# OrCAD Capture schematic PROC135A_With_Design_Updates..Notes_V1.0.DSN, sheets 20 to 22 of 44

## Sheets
20 20. OSPI INTERFACE: size C; title: OSPI INTERFACE
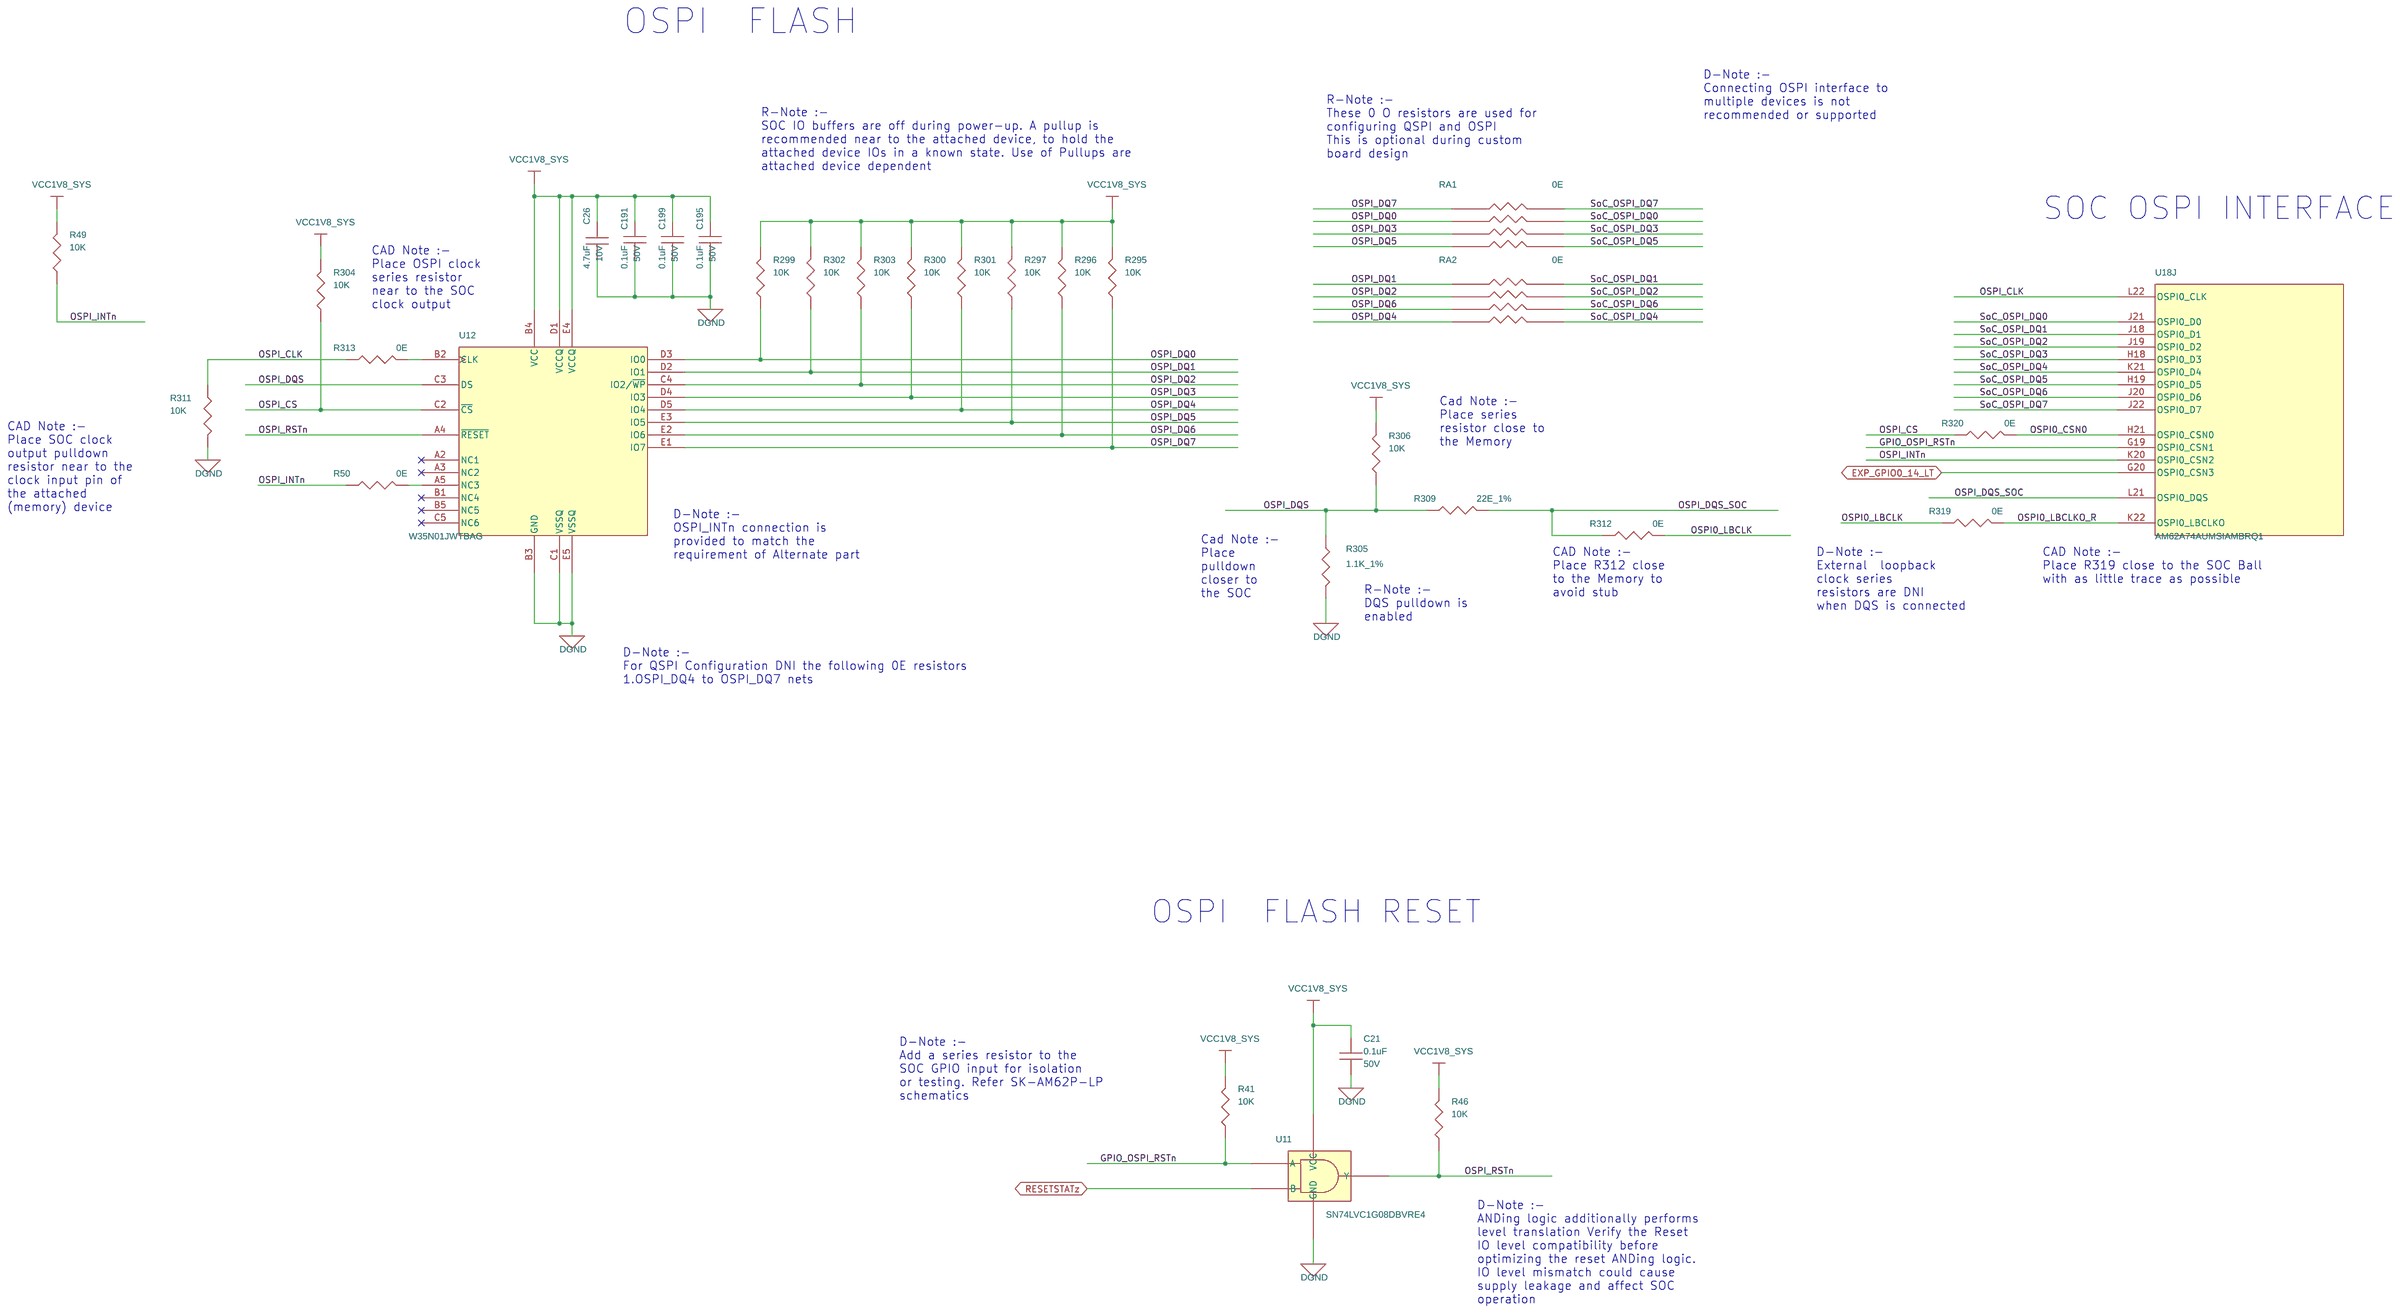
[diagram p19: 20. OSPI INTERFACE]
21 21. BRD ID EEPROM &TEMP SENSORS: size C; title: BOARD ID EEPROM & TEMPERATURE SENSORS
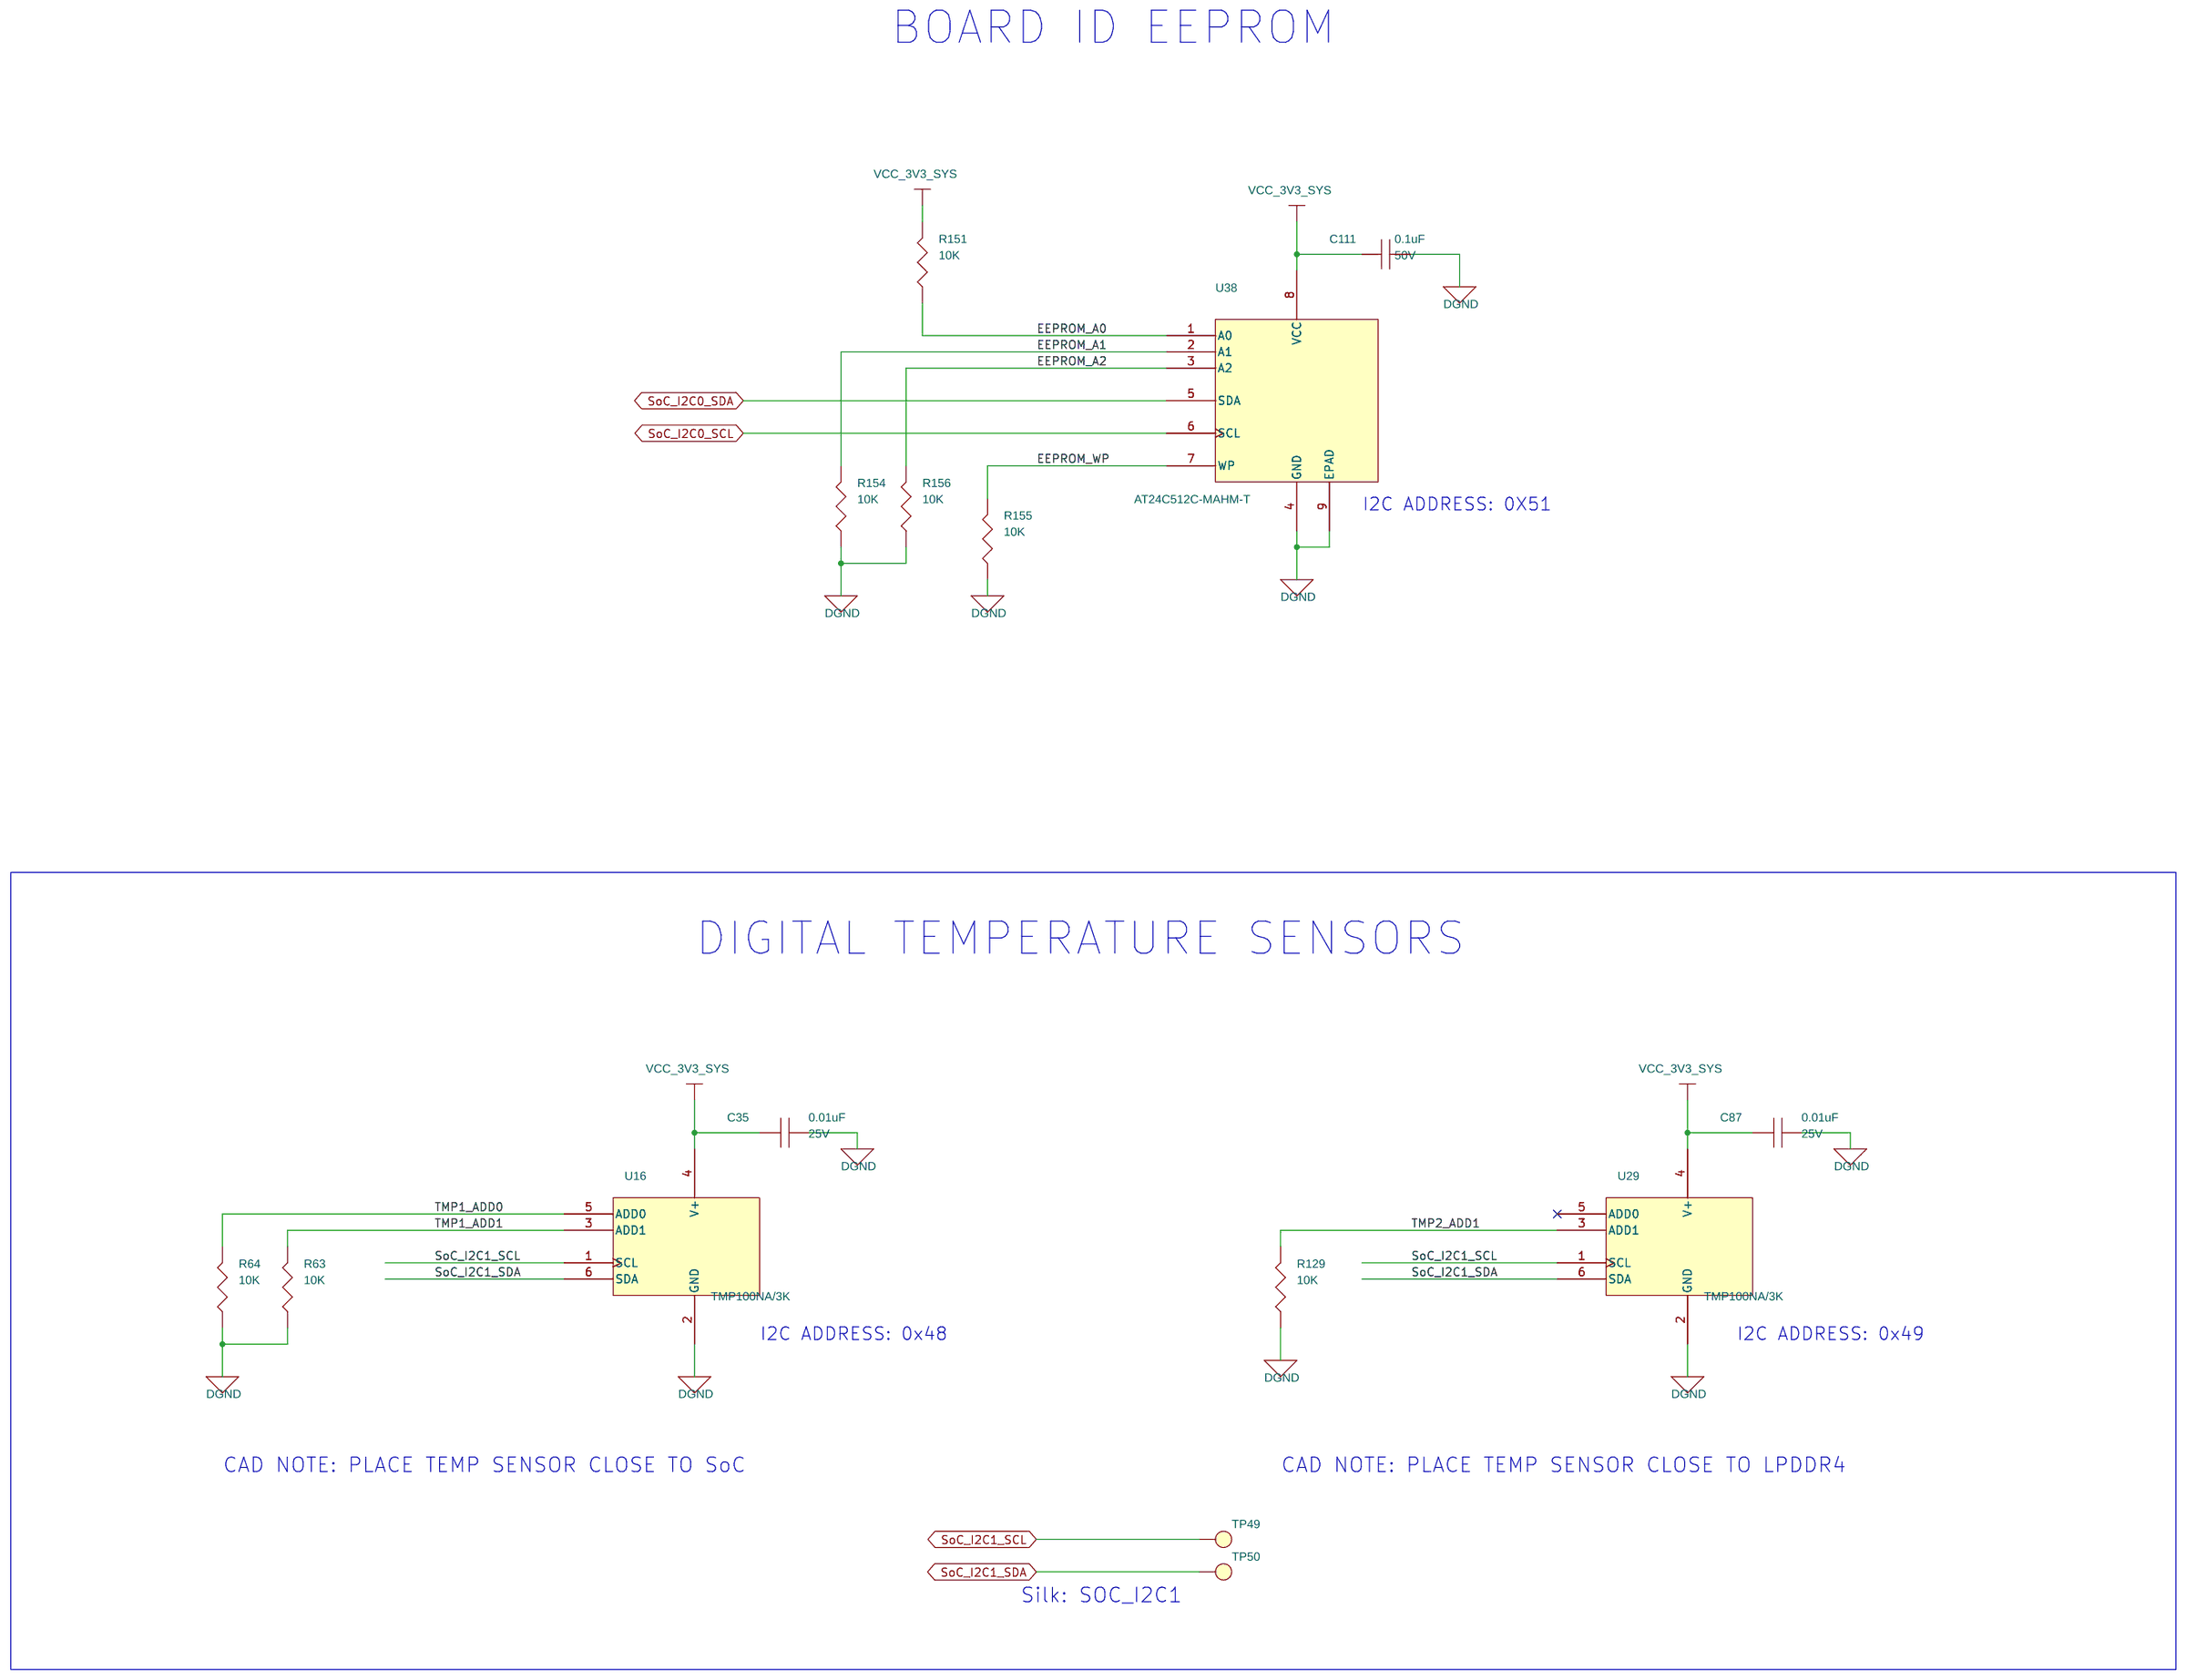
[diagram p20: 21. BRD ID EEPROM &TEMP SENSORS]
22 22. CPSW RGMII_1 ETHERNET PHY: size C; title: CPSW RGMII_1 ETHERNET PHY
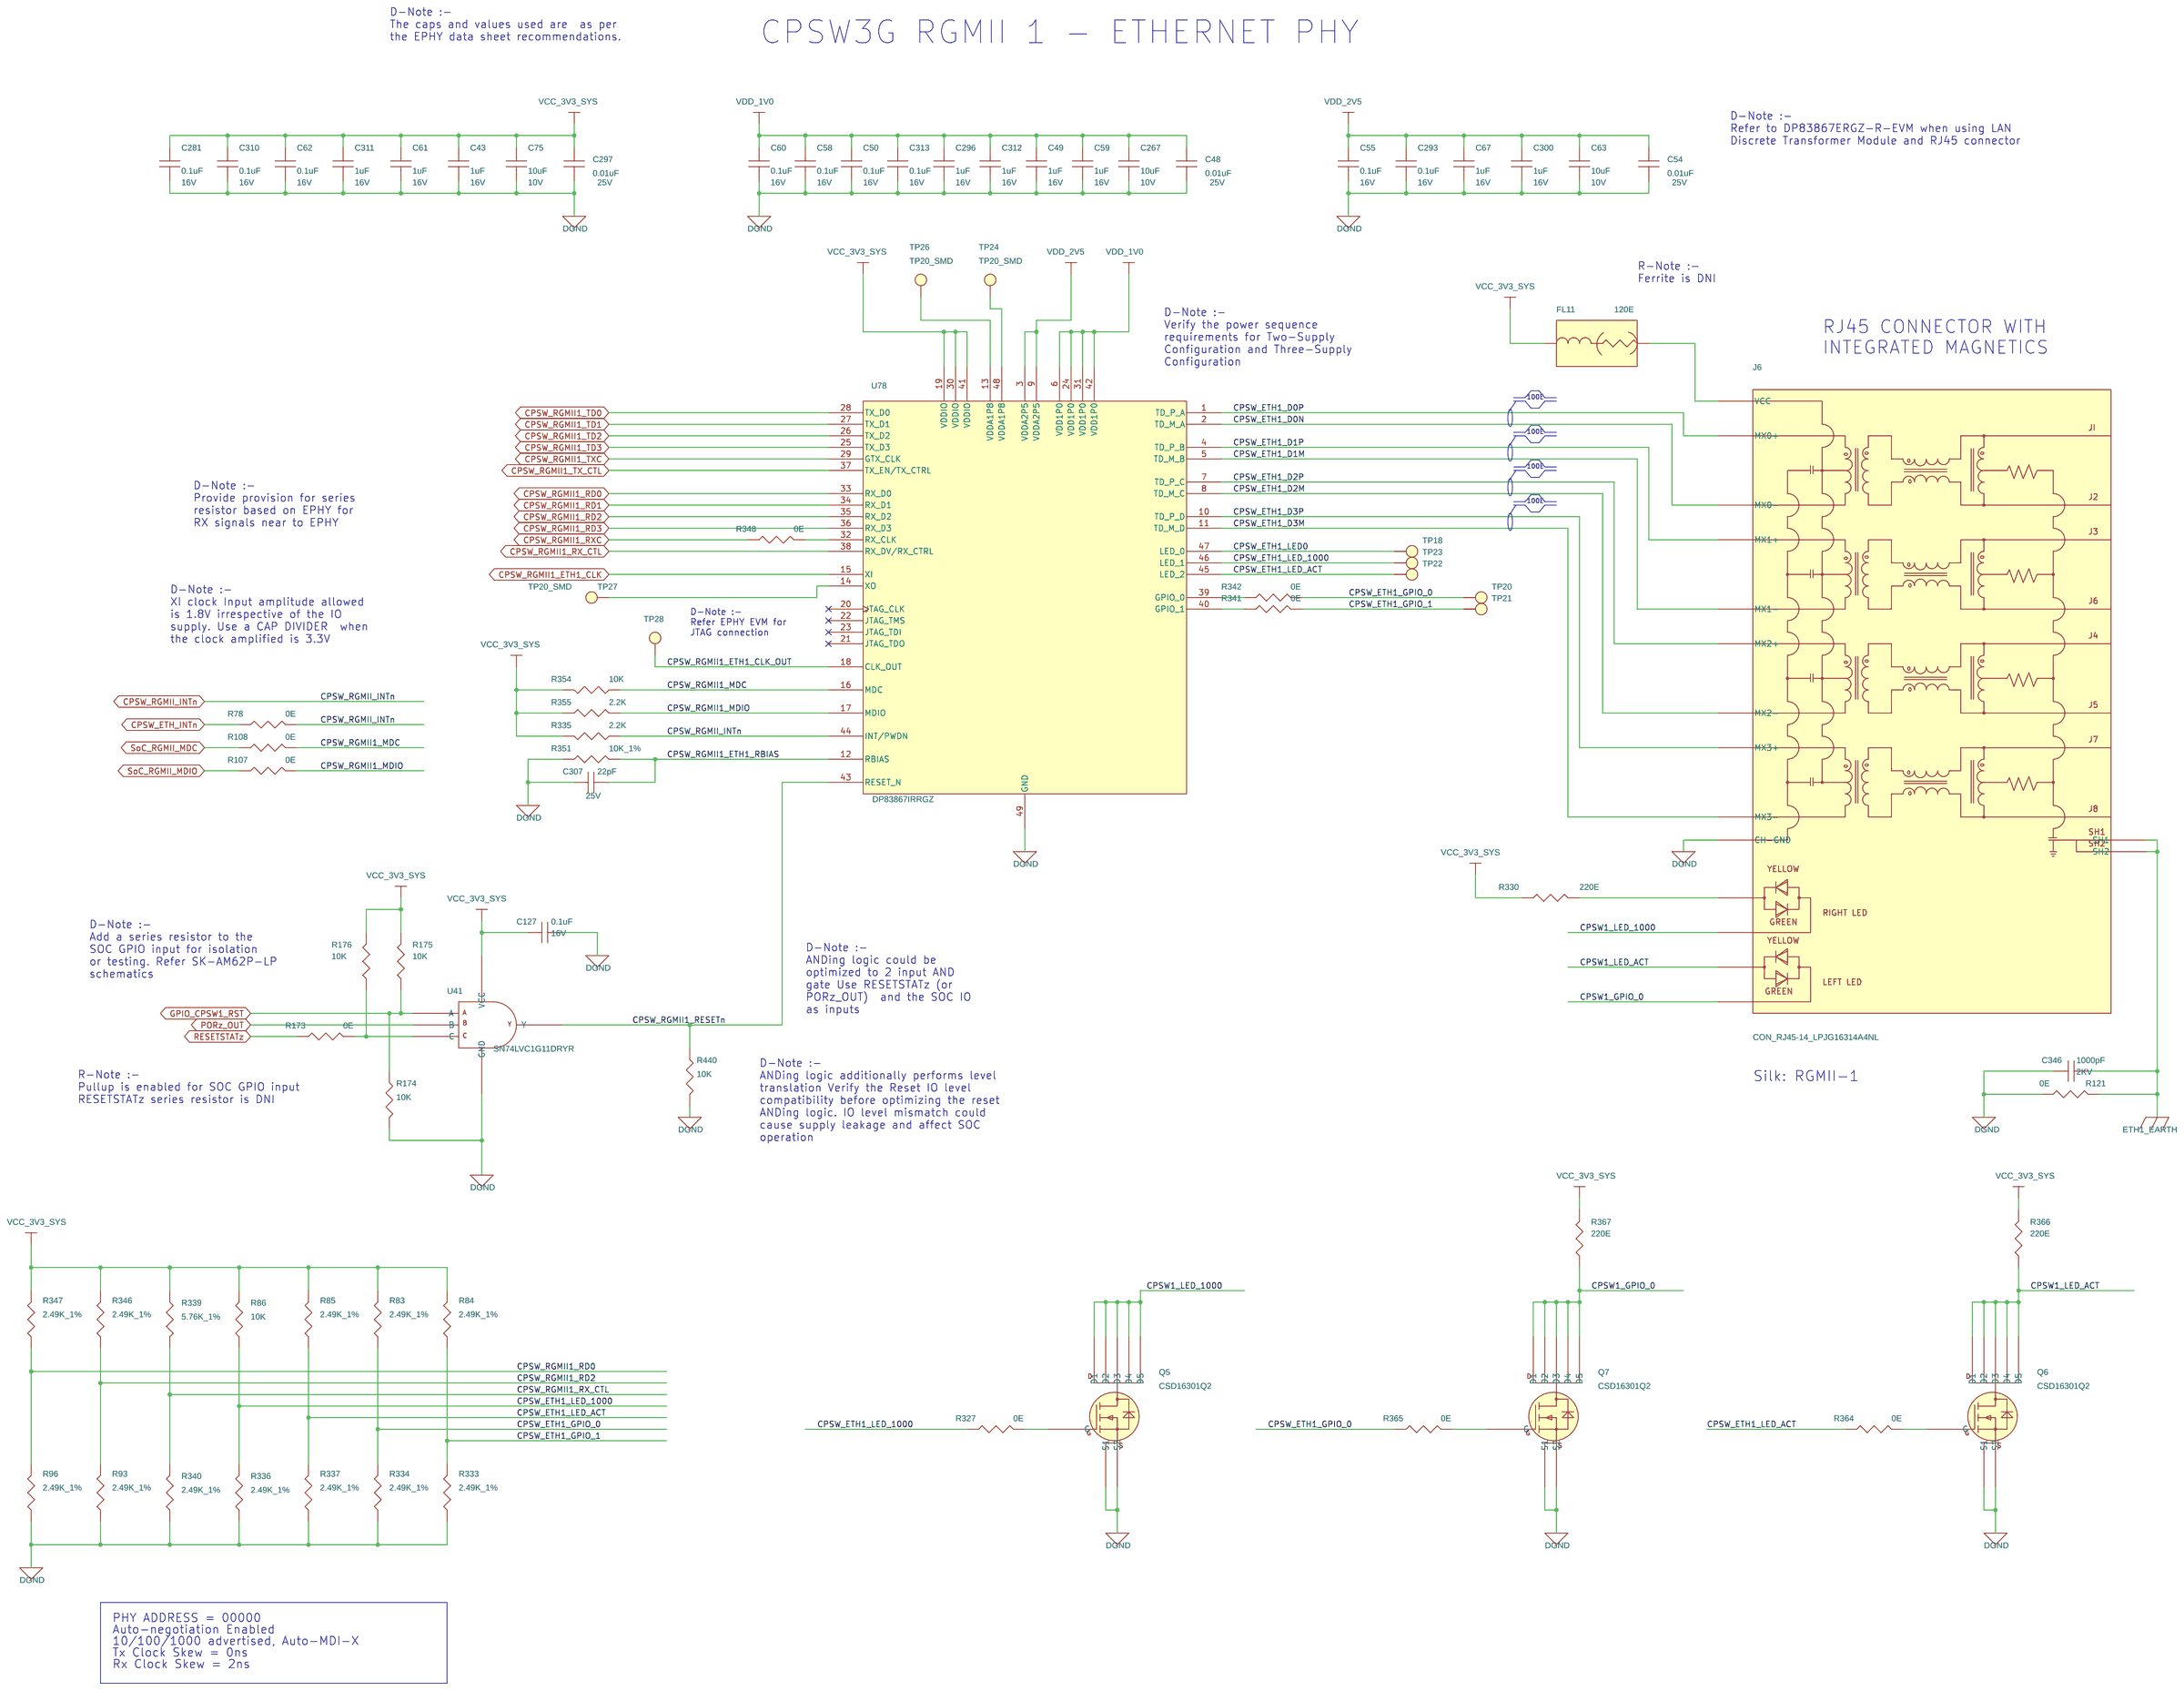
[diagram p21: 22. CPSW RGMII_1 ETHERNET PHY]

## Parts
sheet 20. OSPI INTERFACE
C21  0.1uF  [CAP0402_0-75]
C26  4.7uF  [CAP0402_0-75]
C191  0.1uF  [CAP0402_0-75]
C195  0.1uF  [CAP0402_0-75]
C199  0.1uF  [CAP0402_0-75]
R41  10K  [RES0201_0-5]
R46  10K  [RES0201_0-5]
R49  10K  [RES0201_0-5]
R50  0E  [RES0402_0-5]
R295  10K  [RES0201_0-5]
R296  10K  [RES0201_0-5]
R297  10K  [RES0201_0-5]
R299  10K  [RES0201_0-5]
R300  10K  [RES0201_0-5]
R301  10K  [RES0201_0-5]
R302  10K  [RES0201_0-5]
R303  10K  [RES0201_0-5]
R304  10K  [RES0201_0-5]
R305  1.1K_1%  [RES0201_0-5]
R306  10K  [RES0201_0-5]
R309  22E_1%  [RES0201_0-5]
R311  10K  [RES0201_0-5]
R312  0E  [RES0201_0-5]
R313  0E  [RES0402_0-5]
R319  0E  [RES0201_0-5]
R320  0E  [RES0201_0-5]
RA1  0E  [RESA_EXB_0201-4_0-5]
RA2  0E  [RESA_EXB_0201-4_0-5]
U11  SN74LVC1G08DBVRE4  [SOT23-5]
U12  W35N01JWTBAG  [TPBGA24_39-37_240X320_1-2]
sheet 21. BRD ID EEPROM &TEMP SENSORS
C35  0.01uF  [CAP0201_0-5]
C87  0.01uF  [CAP0201_0-5]
C111  0.1uF  [CAP0402_0-75]
R63  10K  [RES0201_0-5]
R64  10K  [RES0201_0-5]
R129  10K  [RES0201_0-5]
R151  10K  [RES0201_0-5]
R154  10K  [RES0201_0-5]
R155  10K  [RES0201_0-5]
R156  10K  [RES0201_0-5]
TP49  TP20_SMD  [TP20_SMD]
TP50  TP20_SMD  [TP20_SMD]
U16  TMP100NA/3K  [SOT23-6_1-5]
U29  TMP100NA/3K  [SOT23-6_1-5]
U38  AT24C512C-MAHM-T  [UDFN8_19-68_120X80_0-6]
sheet 22. CPSW RGMII_1 ETHERNET PHY
C43  1uF  [CAP0201_0-5]
C48  0.01uF  [CAP0201_0-5]
C49  1uF  [CAP0201_0-5]
C50  0.1uF  [CAP0201_0-5]
C54  0.01uF  [CAP0201_0-5]
C55  0.1uF  [CAP0201_0-5]
C58  0.1uF  [CAP0201_0-5]
C59  1uF  [CAP0201_0-5]
C60  0.1uF  [CAP0201_0-5]
C61  1uF  [CAP0201_0-5]
C62  0.1uF  [CAP0201_0-5]
C63  10uF  [CAP0402_0-75]
C67  1uF  [CAP0201_0-5]
C75  10uF  [CAP0402_0-75]
C127  0.1uF  [CAP0201_0-5]
C267  10uF  [CAP0402_0-75]
C281  0.1uF  [CAP0201_0-5]
C293  0.1uF  [CAP0201_0-5]
C296  1uF  [CAP0201_0-5]
C297  0.01uF  [CAP0201_0-5]
C300  1uF  [CAP0201_0-5]
C307  22pF  [CAP0201_0-5]
C310  0.1uF  [CAP0201_0-5]
C311  1uF  [CAP0201_0-5]
C312  1uF  [CAP0201_0-5]
C313  0.1uF  [CAP0201_0-5]
C346  1000pF  [CAP1206_1-75]
FL11  120E  [EMIFIL_BLM15A_0402_0-6]
J6  CON_RJ45-14_LPJG16314A4NL  [CON_RJ45-14_LPJG16314A4NL_S_R_T_13-6]
Q5  CSD16301Q2  [WSON6_CSD13202Q2_80X80_0-8]
Q6  CSD16301Q2  [WSON6_CSD13202Q2_80X80_0-8]
Q7  CSD16301Q2  [WSON6_CSD13202Q2_80X80_0-8]
R78  0E  [RES0402_0-5]
R83  2.49K_1%  [RES0402_0-5]
R84  2.49K_1%  [RES0402_0-5]
R85  2.49K_1%  [RES0402_0-5]
R86  10K  [RES0201_0-5]
R93  2.49K_1%  [RES0402_0-5]
R96  2.49K_1%  [RES0402_0-5]
R107  0E  [RES0402_0-5]
R108  0E  [RES0402_0-5]
R121  0E  [RES0603_0-75]
R173  0E  [RES0201_0-5]
R174  10K  [RES0201_0-5]
R175  10K  [RES0201_0-5]
R176  10K  [RES0201_0-5]
R327  0E  [RES0201_0-5]
R330  220E  [RES0402_0-5]
R333  2.49K_1%  [RES0402_0-5]
R334  2.49K_1%  [RES0402_0-5]
R335  2.2K  [RES0201_0-5]
R336  2.49K_1%  [RES0402_0-5]
R337  2.49K_1%  [RES0402_0-5]
R339  5.76K_1%  [RES0402_0-5]
R340  2.49K_1%  [RES0402_0-5]
R341  0E  [RES0201_0-5]
R342  0E  [RES0201_0-5]
R346  2.49K_1%  [RES0402_0-5]
R347  2.49K_1%  [RES0402_0-5]
R348  0E  [RES0402_0-5]
R351  10K_1%  [RES0402_0-5]
R354  10K  [RES0201_0-5]
R355  2.2K  [RES0201_0-5]
R364  0E  [RES0201_0-5]
R365  0E  [RES0201_0-5]
R366  220E  [RES0402_0-5]
R367  220E  [RES0402_0-5]
R440  10K  [RES0201_0-5]
TP18  TP20_SMD  [TP20_SMD]
TP20  TP20_SMD  [TP20_SMD]
TP21  TP20_SMD  [TP20_SMD]
TP22  TP20_SMD  [TP20_SMD]
TP23  TP20_SMD  [TP20_SMD]
TP24  TP20_SMD  [TP20_SMD]
TP26  TP20_SMD  [TP20_SMD]
TP27  TP20_SMD  [TP20_SMD]
TP28  TP20_SMD  [TP20_SMD]
U41  SN74LVC1G11DRYR  [SON6_SN74LVC2G17_40X60_0-6]
U78  DP83867IRRGZ  [QFN48_19-68_280X280_1]
sheet 41. OSCILLATOR
U18  AM62A74AUMSIAMBRQ1  [FBGA484_31-49_710X710_2-7]  (sections A,B,C,D,E,F,G,H,I,J,K,L,M,N,O,P,Q)

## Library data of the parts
C21 C111 C191 C195 C199 = CAP: CAP CERAMIC 0.1uF 50V 10% X7R 0402; Alt_Mfr_name: YAGEO AMERICA; Alt_Mfr_part_number: CC0402KRX5R8BB104; Chkd/date: MANIRAJA/261020; Crtd /date: ALVY/211020; Custom_Duty: 15%; Customs_HS_Code: 85322990; Distributor_name: DIGIKEY; Distributor_part_number: 490-10700-1-ND; Footprint Path: Y:\MIS_DATABASE\Library\ALTIUM_TOOL\PCB_FOOTPRINTS\Altium_Footprint_Lib.PcbLib; Height: 0.55MM; Library Path: Y:\MIS_DATABASE\Library\ALTIUM_TOOL\SCHEMATICS_PARTS\MS_DISCRETE_Library.schlib; Mfr_name: MURATA; Mfr_part_number: GRM155R71H104KE14D; Mistral Part No: 120011100014-R; Package: 0402; Part_type: CAPACITORS\CERAMIC; Project: J7_CP; RoHS: RoHS; Temperature: -55°C+125°C; Tolerance: 10%; Voltage: 50V; Wattage: NA; Weight: 3.1mg; Datasheet: Y:\MIS_DATABASE\DATASHEETS\CAPACITORS\GRM155R71H104KE14.PDF
C26 = CAP: CAP CERAMIC 4.7uF 10V 20% X5R 0402; Chkd/date: MANIRAJA/110718; Crtd /date: ALVY/110718; Custom_Duty: 15%; Customs_HS_Code: 85322990; Distributor_name: DIGIKEY; Distributor_part_number: 490-14306-1-ND; Footprint Path: Y:\MIS_DATABASE\Library\ALTIUM_TOOL\PCB_FOOTPRINTS\Altium_Footprint_Lib.PcbLib; Height: 0.65MM; Library Path: Y:\MIS_DATABASE\Library\ALTIUM_TOOL\SCHEMATICS_PARTS\MS_DISCRETE_Library.schlib; Mfr_name: MURATA; Mfr_part_number: GRM155R61A475MEAAD; Mistral Part No: 120012060002-R; Package: 0402; Part_type: CAPACITORS\CERAMIC; Project: TI_J7SVB_PCIE_ADD-ON-CARD; RoHS: RoHS; Temperature: -55°C+85°C; Tolerance: 20%; Voltage: 10V; Wattage: NA; Weight: 14mg; Datasheet: Y:\MIS_DATABASE\DATASHEETS\CAPACITORS\GRM155R61A475MEAAD.PDF
R41 R46 R49 R63 R64 R86 R129 R151 R154-R156 R174-R176 R295-R297 R299-R304 R306 R311 R354 R440 = RESISTOR: RES 10K 1/20W 5% 0201; Chkd/date: MANIRAJA/050517; Crtd /date: MANIRAJA/050517; Custom_Duty: 15%; Customs_HS_Code: 85332119; Distributor_name: DIGIKEY; Distributor_part_number: 311-10KNCT-ND; Footprint Path: Y:\MIS_DATABASE\Library\ALTIUM_TOOL\PCB_FOOTPRINTS\Altium_Footprint_Lib.PcbLib; Height: 0.26MM; Library Path: Y:\MIS_DATABASE\Library\ALTIUM_TOOL\SCHEMATICS_PARTS\MS_DISCRETE_Library.schlib; Mfr_name: YAGEO AMERICA; Mfr_part_number: RC0201JR-0710KL; Mistral Part No: 110010070051-R; Package: 0201; Part_type: RESISTORS\FIXED; Project: GOLDEN-I LITE; RoHS: RoHS; Temperature: -55°C+125°C; Tolerance: 5%; Voltage: NA; Wattage: 1/20W; Weight: 0.17mg; Datasheet: Y:\MIS_DATABASE\DATASHEETS\RESISTORS\RCXXXXL-SER_MAR18.PDF
R50 R78 R107 R108 = RESISTOR: RES 0E 1/16W JUMPER 0402; Chkd/date: VASANTHA/201216; Crtd /date: MUDDU/190810; Custom_Duty: 15%; Customs_HS_Code: 85332119; Distributor_name: DIGIKEY; Distributor_part_number: 541-0.0JCT-ND; Footprint Path: Y:\MIS_DATABASE\Library\ALTIUM_TOOL\PCB_FOOTPRINTS\Altium_Footprint_Lib.PcbLib; Height: 0.40MM; Library Path: Y:\MIS_DATABASE\Library\ALTIUM_TOOL\SCHEMATICS_PARTS\MS_DISCRETE_Library.schlib; Mfr_name: VISHAY; Mfr_part_number: CRCW04020000Z0ED; Mistral Part No: 110010080019-R; Package: 0402; Part_type: RESISTORS\FIXED; Project: PB_BUGBASE; RoHS: RoHS; Temperature: -55°C+155°C; Tolerance: NA; Voltage: NA; Wattage: 1/16W; Weight: 0.65mg; Datasheet: Y:\MIS_DATABASE\DATASHEETS\RESISTORS\CRCW0603.PDF
R305 = RESISTOR: RES 1.1K 1/20W 1% 0201; Chkd/date: MANIRAJA/270721; Crtd /date: ALVY/260721; Custom_Duty: 15%; Customs_HS_Code: 85332119; Distributor_name: DIGIKEY; Distributor_part_number: YAG2474CT-ND; Footprint Path: Y:\MIS_DATABASE\Library\ALTIUM_TOOL\PCB_FOOTPRINTS\Altium_Footprint_Lib.PcbLib; Height: 0.26MM; Library Path: Y:\MIS_DATABASE\Library\ALTIUM_TOOL\SCHEMATICS_PARTS\MS_DISCRETE_Library.schlib; Mfr_name: YAGEO AMERICA; Mfr_part_number: RC0201FR-071K1L; Mistral Part No: 110009030097-R; Package: 0201; Part_type: RESISTORS\FIXED; Project: TI_AM335x SK_BRD; RoHS: RoHS; Temperature: -55°C+125°C; Tolerance: 1%; Voltage: NA; Wattage: 1/20W; Weight: 0.17mg; Datasheet: Y:\MIS_DATABASE\DATASHEETS\RESISTORS\RCXXXXL-SER_MAR18.PDF
R309 = RESISTOR: RES 22E 1/20W 1% 0201; Chkd/date: MANIRAJA/080319; Crtd /date: ALVY/080319; Custom_Duty: 15%; Customs_HS_Code: 85332119; Distributor_name: DIGIKEY; Distributor_part_number: YAG2518CT-ND; Footprint Path: Y:\MIS_DATABASE\Library\ALTIUM_TOOL\PCB_FOOTPRINTS\Altium_Footprint_Lib.PcbLib; Height: 0.26MM; Library Path: Y:\MIS_DATABASE\Library\ALTIUM_TOOL\SCHEMATICS_PARTS\MS_DISCRETE_Library.schlib; Mfr_name: YAGEO AMERICA; Mfr_part_number: RC0201FR-0722RL; Mistral Part No: 110009030522-R; Package: 0201; Part_type: RESISTORS\FIXED; Project: AM654x_SOM; RoHS: RoHS; SIGNAL_MODEL: RESISTOR_RES0201_0-5_22E_1%_22E_1%; Temperature: -55°C+125°C; Tolerance: 1%; Voltage: NA; Wattage: 1/20W; Weight: 0.17mg; Datasheet: Y:\MIS_DATABASE\DATASHEETS\RESISTORS\RCXXXXL-SER_MAR18.PDF
R312 R319 = RESISTOR: RES 0E 1/20W 5% 0201; Chkd/date: NAVEED/301214; Crtd /date: MUDDU/120710; Custom_Duty: 15%; Customs_HS_Code: 85332119; Distributor_name: DIGIKEY; Distributor_part_number: 311-0.0NCT-ND; Footprint Path: Y:\MIS_DATABASE\Library\ALTIUM_TOOL\PCB_FOOTPRINTS\Altium_Footprint_Lib.PcbLib; Height: 0.26MM; Library Path: Y:\MIS_DATABASE\Library\ALTIUM_TOOL\SCHEMATICS_PARTS\MS_DISCRETE_Library.schlib; Mfr_name: YAGEO AMERICA; Mfr_part_number: RC0201JR-070RL; Mistral Part No: 110010070067-R; Package: 0201; Part_type: RESISTORS\FIXED; Project: PB_BUGBASE; RoHS: RoHS; SIGNAL_MODEL: RESISTOR_RES0201_0-5_0E_0E; Temperature: -55°C+125°C; Tolerance: 5%; Voltage: NA; Wattage: 1/20W; Weight: 0.17mg; Datasheet: Y:\MIS_DATABASE\DATASHEETS\RESISTORS\RCXXXXL-SER_MAR18.PDF
R313 R348 = RESISTOR: RES 0E 1/16W JUMPER 0402; Chkd/date: VASANTHA/201216; Crtd /date: MUDDU/190810; Custom_Duty: 15%; Customs_HS_Code: 85332119; Distributor_name: DIGIKEY; Distributor_part_number: 541-0.0JCT-ND; Footprint Path: Y:\MIS_DATABASE\Library\ALTIUM_TOOL\PCB_FOOTPRINTS\Altium_Footprint_Lib.PcbLib; Height: 0.40MM; Library Path: Y:\MIS_DATABASE\Library\ALTIUM_TOOL\SCHEMATICS_PARTS\MS_DISCRETE_Library.schlib; Mfr_name: VISHAY; Mfr_part_number: CRCW04020000Z0ED; Mistral Part No: 110010080019-R; Package: 0402; Part_type: RESISTORS\FIXED; Project: PB_BUGBASE; RoHS: RoHS; SIGNAL_MODEL: RESISTOR_RES0402_0-5_0E_0E; Temperature: -55°C+155°C; Tolerance: NA; Voltage: NA; Wattage: 1/16W; Weight: 0.65mg; Datasheet: Y:\MIS_DATABASE\DATASHEETS\RESISTORS\CRCW0603.PDF
R173 R320 R327 R341 R342 R364 R365 = RESISTOR: RES 0E 1/20W 5% 0201; Chkd/date: NAVEED/301214; Crtd /date: MUDDU/120710; Custom_Duty: 15%; Customs_HS_Code: 85332119; Distributor_name: DIGIKEY; Distributor_part_number: 311-0.0NCT-ND; Footprint Path: Y:\MIS_DATABASE\Library\ALTIUM_TOOL\PCB_FOOTPRINTS\Altium_Footprint_Lib.PcbLib; Height: 0.26MM; Library Path: Y:\MIS_DATABASE\Library\ALTIUM_TOOL\SCHEMATICS_PARTS\MS_DISCRETE_Library.schlib; Mfr_name: YAGEO AMERICA; Mfr_part_number: RC0201JR-070RL; Mistral Part No: 110010070067-R; Package: 0201; Part_type: RESISTORS\FIXED; Project: PB_BUGBASE; RoHS: RoHS; Temperature: -55°C+125°C; Tolerance: 5%; Voltage: NA; Wattage: 1/20W; Weight: 0.17mg; Datasheet: Y:\MIS_DATABASE\DATASHEETS\RESISTORS\RCXXXXL-SER_MAR18.PDF
RA1 RA2 = RESARR_ISO4: RES ARRAY 0E 31mW JUMPER 0201-4; Chkd/date: MANIRAJA/290918; Crtd /date: MANIRAJA/290918; Custom_Duty: 15%; Customs_HS_Code: 85332119; Distributor_name: DIGIKEY; Distributor_part_number: Y6000CT-ND; Footprint Path: Y:\MIS_DATABASE\Library\ALTIUM_TOOL\PCB_FOOTPRINTS\Altium_Footprint_Lib.PcbLib; Height: 0.45MM; Library Path: Y:\MIS_DATABASE\Library\ALTIUM_TOOL\SCHEMATICS_PARTS\MS_DISCRETE_Library.schlib; Manufacturer: PANASONIC-ECG; Mfr_name: PANASONIC-ECG; Mfr_part_number: EXB-18VR000X; Mistral Part No: 110018090033-R; Package: 0201-4; Part_type: RESISTORS\ARRAY; Project: TI_60GHz-AOP; RoHS: RoHS; SIGNAL_MODEL: RESARR_ISO4_RESA_EXB_0201-4_0-5_0E; Temperature: -55°C+125°C; Tolerance: NA; Voltage: NA; Wattage: 31mW; Weight: 1mg; Datasheet: Y:\MIS_DATABASE\DATASHEETS\RESISTORS\EXB-18V.PDF
U11 = SN74LVC1G08DBVRE4_SOT23-5: IC SINGLE 2-INPUT POSITIVE AND GATE SOT23-5; Chkd/date: SUHAS/221010; Crtd /date: USMAN/151008; Custom_Duty: 15%; Customs_HS_Code: 85423100; Distributor_name: DIGIKEY; Distributor_part_number: SN74LVC1G08DBVRE4-ND; Height: 1.45MM; Mfr_name: TEXAS INSTRUMENTS; Mistral Part No: 141009060026-R; Part_type: ICS\DIGITAL\GATES; Project: KHAN_MAIN; RoHS: Sb/ Br FREE; Temperature: -40°C+85°C; Datasheet: Y:\MIS_DATABASE\DATASHEETS\ICS\DIGITAL\GATES\SN74LVC1G08.PDF
U12 = W35N01JWTB_TFBGA24: IC 1.7-1.95V 1Gb SERIAL SLC NAND FLASH MEMORY OCTAL SPI TFBGA24; Chkd/date: MANIRAJA/090421; Crtd /date: ALVY/080421; Custom_Duty: 15%; Customs_HS_Code: 85423100; Distributor_name: NA; Distributor_part_number: NA; Footprint Path: Y:\MIS_DATABASE\Library\ALTIUM_TOOL\PCB_FOOTPRINTS\Altium_Footprint_Lib.PcbLib; Height: 1.20MM; Library Path: Y:\MIS_DATABASE\Library\ALTIUM_TOOL\SCHEMATICS_PARTS\MS_MISCMEMORY_Library.schlib; Mfr_name: WINBOND; Mistral Part No: 141121040002-R; Package: TFBGA24; Part_type: ICS\DIGITAL\MEMORY; Project: TI_J7AEP SOM BRD; RoHS: RoHS; Temperature: -40°C+105°C; Tolerance: NA; Voltage: NA; Wattage: NA; Weight: NA; Datasheet: Y:\MIS_DATABASE\DATASHEETS\ICS\MEMORY\W35N01JWXX.PDF
C35 C48 C54 C87 C297 = CAP: CAP CERAMIC 0.01uF 25V 10% X5R 0201; Chkd/date: MANIRAJA/230118; Crtd /date: MANIRAJA/230118; Custom_Duty: 15%; Customs_HS_Code: 85322990; Distributor_name: DIGIKEY; Distributor_part_number: GRM033R61E103KA12J-ND; Footprint Path: Y:\MIS_DATABASE\Library\ALTIUM_TOOL\PCB_FOOTPRINTS\Altium_Footprint_Lib.PcbLib; Height: 0.33MM; Library Path: Y:\MIS_DATABASE\Library\ALTIUM_TOOL\SCHEMATICS_PARTS\MS_DISCRETE_Library.schlib; Mfr_name: MURATA; Mfr_part_number: GRM033R61E103KA12J; Mistral Part No: 120018010007-R; Package: 0201; Part_type: CAPACITORS\CERAMIC; Project: TI_MAXIE_CPB; RoHS: RoHS; Temperature: -55°C+85°C; Tolerance: 10%; Voltage: 25V; Wattage: NA; Weight: 0.33mg; Datasheet: Y:\MIS_DATABASE\DATASHEETS\CAPACITORS\GRM033R61E103KA12.PDF
TP18 TP20-TP23 TP28 TP49 TP50 = TESTPOINT: TESTPOINT CIR 20 SMD; Chkd/date: SHREESHAIL/171006; Crtd /date: MAZHAR/171006; Custom_Duty: NA; Customs_HS_Code: NA; Distributor_name: NA; Distributor_part_number: NA; Footprint Path: Y:\MIS_DATABASE\Library\ALTIUM_TOOL\PCB_FOOTPRINTS\Altium_Footprint_Lib.PcbLib; Height: NA; Library Path: Y:\MIS_DATABASE\Library\ALTIUM_TOOL\SCHEMATICS_PARTS\MS_DISCRETE_Library.schlib; MECHANICAL 3D STEP FILE: NA; Mfr_name: LOCAL; Mistral Part No: NA; Package: SMD; Project: BT MODULE_CSRBC04; RoHS: NA; Temperature: NA; Tolerance: NA; Voltage: NA; Wattage: NA; Weight: NA; Datasheet: NA
U16 U29 = TMP100NA_3K_SOT23-6: IC TEMPERATURE SENSOR WITH I2C AND SMBUS INTERFACE SOT23-6; Chkd/date: MANIRAJA/290817; Crtd /date: MANIRAJA/290817; Custom_Duty: 15%; Customs_HS_Code: 85423100; Distributor_name: DIGIKEY; Distributor_part_number: 296-26833-1-ND; Height: 1.45MM; Library Ref: TMP100NA/3K_SOT23-6; Mfr_name: TEXAS INSTRUMENTS; Mistral Part No: 141017080030-R; Package: SOT23-6; Part_type: ICS\DIGITAL\PERIPHERAL; Project: TI_MAXIE_CPB; RoHS: RoHS; Temperature: -55°C+125°C; Tolerance: NA; Voltage: NA; Wattage: NA; Weight: 120mg; Datasheet: Y:\MIS_DATABASE\DATASHEETS\ICS\DIGITAL\PERIPHERAL\TMP10XX.PDF
U38 = AT24C64D-MAHM-T_UDFN8: IC 1.7-3.6V 512Kb I2C COMPATIBLE SERIAL EEPROM UDFN8; Chkd/date: MANIRAJA/240919; Crtd /date: ALVY/240919; Custom_Duty: 15%; Customs_HS_Code: 85423100; Distributor_name: DIGIKEY; Distributor_part_number: AT24C512C-MAHM-TCT-ND; Footprint Path: Y:\MIS_DATABASE\Library\ALTIUM_TOOL\PCB_FOOTPRINTS\Altium_Footprint_Lib.PcbLib; Height: 0.60MM; Library Path: Y:\MIS_DATABASE\Library\ALTIUM_TOOL\SCHEMATICS_PARTS\MS_MISCMEMORY_Library.schlib; Mfr_name: MICROCHIP; Mistral Part No: 141119090004-R; Package: UDFN8; Part_type: ICS\DIGITAL\MEMORY; Project: HAL_3U-T1042-SBC; RoHS: RoHS; Temperature: -40°C+85°C; Tolerance: NA; Voltage: NA; Wattage: NA; Weight: 9.5mg; Datasheet: Y:\MIS_DATABASE\DATASHEETS\ICS\MEMORY\AT24C512C.PDF
C43 C49 C59 C61 C67 C296 C300 C311 C312 = CAP: CAP CERAMIC 1uF 16V 20% X5R 0201; Chkd/date: MANIRAJA/300520; Crtd /date: ALVY/260520; Custom_Duty: 15%; Customs_HS_Code: 85322990; Distributor_name: DIGIKEY; Distributor_part_number: 490-18654-1-ND; Footprint Path: Y:\MIS_DATABASE\Library\ALTIUM_TOOL\PCB_FOOTPRINTS\Altium_Footprint_Lib.PcbLib; Height: 0.39MM; Library Path: Y:\MIS_DATABASE\Library\ALTIUM_TOOL\SCHEMATICS_PARTS\MS_DISCRETE_Library.schlib; Mfr_name: MURATA; Mfr_part_number: GRM033R61C105ME15D; Mistral Part No: 120018090038-R; Package: 0201; Part_type: CAPACITORS\CERAMIC; Project: QCS610_NANOSOM; RoHS: RoHS; Temperature: -55°C+85°C; Tolerance: 20%; Voltage: 16V; Wattage: NA; Weight: 0.33mg; Datasheet: Y:\MIS_DATABASE\DATASHEETS\CAPACITORS\GRM033R61C105ME15.PDF
C50 C55 C58 C60 C62 C127 C281 C293 C310 C313 = CAP: CAP CERAMIC 0.1uF 16V 10% X5R 0201; Alt_Mfr_name: YAGEO AMERICA; Alt_Mfr_part_number: CC0402KRX5R8BB104; Chkd/date: MANIRAJA/230118; Crtd /date: MANIRAJA/230118; Custom_Duty: 15%; Customs_HS_Code: 85322990; Distributor_name: DIGIKEY; Distributor_part_number: 490-14305-1-ND; Footprint Path: Y:\MIS_DATABASE\Library\ALTIUM_TOOL\PCB_FOOTPRINTS\Altium_Footprint_Lib.PcbLib; Height: 0.33MM; Library Path: Y:\MIS_DATABASE\Library\ALTIUM_TOOL\SCHEMATICS_PARTS\MS_DISCRETE_Library.schlib; Mfr_name: MURATA; Mfr_part_number: GRM033R61C104KE14D; Mistral Part No: 120009030072-R; Package: 0201; Part_type: CAPACITORS\CERAMIC; Project: TI_MAXIE_CPB; RoHS: RoHS; Temperature: -55°C+85°C; Tolerance: 10%; Voltage: 16V; Wattage: NA; Weight: 0.33mg; Datasheet: Y:\MIS_DATABASE\DATASHEETS\CAPACITORS\GRM033R61C104KE14.PDF
C63 C75 C267 = CAP: CAP CERAMIC 10uF 10V 20% X5R 0402; Chkd/date: MANIRAJA/300520; Crtd /date: ALVY/260520; Custom_Duty: 15%; Customs_HS_Code: 85322990; Distributor_name: DIGIKEY; Distributor_part_number: 490-GRM155R61A106ME11DTR-ND; Footprint Path: Y:\MIS_DATABASE\Library\ALTIUM_TOOL\PCB_FOOTPRINTS\Altium_Footprint_Lib.PcbLib; Height: 0.55MM; Library Path: Y:\MIS_DATABASE\Library\ALTIUM_TOOL\SCHEMATICS_PARTS\MS_DISCRETE_Library.schlib; Mfr_name: MURATA; Mfr_part_number: GRM155R61A106ME11D; Mistral Part No: 120013110019-R; Package: 0402; Part_type: CAPACITORS\CERAMIC; Project: QCS610_NANOSOM; RoHS: RoHS; Temperature: -55°C+85°C; Tolerance: 20%; Voltage: 10V; Wattage: NA; Weight: 3.1mg; Datasheet: Y:\MIS_DATABASE\DATASHEETS\CAPACITORS\MURATA-GXX-SER_NOV17.PDF
C307 = CAP: CAP CERAMIC 22pF 25V 1% C0G(NP0) 0201; Chkd/date: MANIRAJA/270721; Crtd /date: ALVY/260721; Custom_Duty: 15%; Customs_HS_Code: 85322990; Distributor_name: DIGIKEY; Distributor_part_number: 490-14545-1-ND; Footprint Path: Y:\MIS_DATABASE\Library\ALTIUM_TOOL\PCB_FOOTPRINTS\Altium_Footprint_Lib.PcbLib; Height: 0.33MM; Library Path: Y:\MIS_DATABASE\Library\ALTIUM_TOOL\SCHEMATICS_PARTS\MS_DISCRETE_Library.schlib; Mfr_name: MURATA; Mfr_part_number: GRM0335C1E220FA01D; Mistral Part No: 120021070019-R; Package: 0201; Part_type: CAPACITORS\CERAMIC; Project: TI_AM335x SK_BRD; RoHS: RoHS; Temperature: -55°C+125°C; Tolerance: 1%; Voltage: 25V; Wattage: NA; Weight: 0.33mg; Datasheet: Y:\MIS_DATABASE\DATASHEETS\CAPACITORS\GRM0335C1E220FA01.PDF
C346 = CAP: CAP CERAMIC 1000pF 2KV 10% X7R 1206; Chkd/date: SHREESHAIL/291106; Crtd /date: MAZHAR/281106; Custom_Duty: 15%; Customs_HS_Code: 85322990; Distributor_name: DIGIKEY; Distributor_part_number: 478-2956-1-ND; Footprint Path: Y:\MIS_DATABASE\Library\ALTIUM_TOOL\PCB_FOOTPRINTS\Altium_Footprint_Lib.PcbLib; Height: 1.52MM; Library Path: Y:\MIS_DATABASE\Library\ALTIUM_TOOL\SCHEMATICS_PARTS\MS_DISCRETE_Library.schlib; Mfr_name: AVX CORPORATION; Mfr_part_number: 1206GC102KAT1A; Mistral Part No: 120015080006-R; Package: 1206; Part_type: CAPACITORS\CERAMIC; Project: ADR1B; RoHS: RoHS; Temperature: -55°C+125°C; Tolerance: 10%; Voltage: 2KV; Wattage: NA; Weight: 16.2mg; Datasheet: Y:\MIS_DATABASE\DATASHEETS\CAPACITORS\AVX_HV-MLC.PDF
FL11 = EMIFILTER_IND: IND FERRITE BEAD CHIP 120E 2A 0402; Chkd/date: NAVEED/241114; Crtd /date: USMAN/170613; Custom_Duty: 24%; Customs_HS_Code: 85369090; Distributor_name: DIGIKEY; Distributor_part_number: 490-9656-1-ND; Footprint Path: Y:\MIS_DATABASE\Library\ALTIUM_TOOL\PCB_FOOTPRINTS\Altium_Footprint_Lib.PcbLib; Height: 0.55MM; Library Path: Y:\MIS_DATABASE\Library\ALTIUM_TOOL\SCHEMATICS_PARTS\MS_FILTER_Library.schlib; Mfr_name: MURATA; Mfr_part_number: BLM15PX121SN1D; Mistral Part No: 130013060022-R; Package: 0402; Part_type: INDUCTOR; Project: GEN_3-8; RoHS: RoHS; Temperature: -55°C+125°C; Tolerance: 25%; Voltage: NA; Wattage: NA; Weight: 1mg; Datasheet: Y:\MIS_DATABASE\DATASHEETS\DISCRETES\INDUCTORS\BLM15-SN1-SER.PDF
J6 = CON_RJ45-14_LPJG16314A4NL: CON RJ-45 FEMALE 14POS RT TH; Chkd/date: VASANTHA/150714; Crtd /date: BALACHANDAR/120614; Custom_Duty: 24%; Customs_HS_Code: 85369090; Distributor_name: NA; Distributor_part_number: NA; Footprint Path: Y:\MIS_DATABASE\Library\ALTIUM_TOOL\PCB_FOOTPRINTS\Altium_Footprint_Lib.PcbLib; Height: 13.60MM; Library Path: Y:\MIS_DATABASE\Library\ALTIUM_TOOL\SCHEMATICS_PARTS\MS_CONNECTOR_Library.schlib; Mfr_name: LINK-PP; Mfr_part_number: LPJG16314A4NL; Mistral Part No: 150014060029-R; Package: THRU-HOLE; Part_type: CONNECTOR\JACK; Project: AEGIS; RoHS: RoHS; Temperature: -0°C+70°C; Tolerance: NA; Voltage: NA; Wattage: NA; Weight: NA; Datasheet: Y:\MIS_DATABASE\DATASHEETS\CONNECTORS\LPJG16314A4NL.PDF
Q5-Q7 = MOSFET_CSD17313Q2: IC MOSFET N-CHANNEL NEXFET 25V WSON6; Chkd/date: ALVY/071220; Crtd /date: MANIRAJA/071220; Custom_Duty: 15%; Customs_HS_Code: 85423100; Distributor_name: DIGIKEY; Distributor_part_number: 296-25260-1-ND; Footprint Path: Y:\MIS_DATABASE\Library\ALTIUM_TOOL\PCB_FOOTPRINTS\Altium_Footprint_Lib.PcbLib; Height: 0.80MM; Library Path: Y:\MIS_DATABASE\Library\ALTIUM_TOOL\SCHEMATICS_PARTS\MS_MOSFET_Library.schlib; Manufacturer: TEXAS INSTRUMENTS; Mfr_name: TEXAS INSTRUMENTS; Mistral Part No: 142020120008-R; Package: WSON6; Part_type: ICS\POWER\MOSFET; Project: TI_AM243x LP EVM; RoHS: RoHS; Temperature: -55°C+150°C; Tolerance: NA; Voltage: NA; Wattage: NA; Weight: 8.7mg; Datasheet: Y:\MIS_DATABASE\DATASHEETS\ICS\POWER\CSD16301Q2.PDF
R83-R85 R93 R96 R333 R334 R336 R337 R340 R346 R347 = RESISTOR: RES 2.49K 1/16W 1% 0402; Chkd/date: VASANTHA/270516; Crtd /date: VASANTHA/270516; Custom_Duty: 15%; Customs_HS_Code: 85332119; Distributor_name: DIGIKEY; Distributor_part_number: 311-2.49KLRCT-ND; Footprint Path: Y:\MIS_DATABASE\Library\ALTIUM_TOOL\PCB_FOOTPRINTS\Altium_Footprint_Lib.PcbLib; Height: 0.40MM; Library Path: Y:\MIS_DATABASE\Library\ALTIUM_TOOL\SCHEMATICS_PARTS\MS_DISCRETE_Library.schlib; Mfr_name: YAGEO AMERICA; Mfr_part_number: RC0402FR-072K49L; Mistral Part No: 110016050020-R; Package: 0402; Part_type: RESISTORS\FIXED; Project: TMDXCSKCC; RoHS: RoHS; Temperature: -55°C+155°C; Tolerance: 1%; Voltage: NA; Wattage: 1/16W; Weight: 0.65mg; Datasheet: Y:\MIS_DATABASE\DATASHEETS\RESISTORS\RCXXXXL-SER_MAR18.PDF
R121 = RESISTOR: RES 0E 1/10W 5% 0603; Chkd/date: MANIRAJA/051217; Crtd /date: BAVISH/180211; Custom_Duty: 15%; Customs_HS_Code: 85332119; Distributor_name: DIGIKEY; Distributor_part_number: 311-0.0GRCT-ND; Footprint Path: Y:\MIS_DATABASE\Library\ALTIUM_TOOL\PCB_FOOTPRINTS\Altium_Footprint_Lib.PcbLib; Height: 0.55MM; Library Path: Y:\MIS_DATABASE\Library\ALTIUM_TOOL\SCHEMATICS_PARTS\MS_DISCRETE_Library.schlib; Manufacturer: YAGEO AMERICA; Mfr_name: PANASONIC-ECG; Mfr_part_number: RC0603JR-070RL; Mistral Part No: 110011020013-R; Package: 0603; Part_type: RESISTORS\FIXED; Project: KENNEL; RoHS: RoHS; Temperature: -55°C+155°C; Tolerance: 5%; Voltage: NA; Wattage: 1/10W; Weight: 2mg; Datasheet: Y:\MIS_DATABASE\DATASHEETS\RESISTORS\RCXXXXL-SER_MAR18.PDF
R330 R366 R367 = RESISTOR: RES 220E 1/10W 5% 0402; Chkd/date: VASANTHA/291216; Crtd /date: GEETHA/260406; Custom_Duty: 15%; Customs_HS_Code: 85332119; Distributor_name: DIGIKEY; Distributor_part_number: P220JCT-ND; Footprint Path: Y:\MIS_DATABASE\Library\ALTIUM_TOOL\PCB_FOOTPRINTS\Altium_Footprint_Lib.PcbLib; Height: 0.40MM; Library Path: Y:\MIS_DATABASE\Library\ALTIUM_TOOL\SCHEMATICS_PARTS\MS_DISCRETE_Library.schlib; Mfr_name: PANASONIC-ECG; Mfr_part_number: ERJ-2GEJ221X; Mistral Part No: 110009030506-R; Package: 0402; Part_type: RESISTORS\FIXED; Project: RED EYE; RoHS: RoHS; Temperature: -55°C+155°C; Tolerance: 5%; Voltage: NA; Wattage: 1/10W; Weight: 0.8mg; Datasheet: Y:\MIS_DATABASE\DATASHEETS\RESISTORS\PAN-ERJSER_NOV17.PDF
R335 R355 = RESISTOR: RES 2.2K 1/20W 5% 0201; Chkd/date: MANIRAJA/050517; Crtd /date: MANIRAJA/050517; Custom_Duty: 15%; Customs_HS_Code: 85332119; Distributor_name: DIGIKEY; Distributor_part_number: 311-2.2KNCT-ND; Footprint Path: Y:\MIS_DATABASE\Library\ALTIUM_TOOL\PCB_FOOTPRINTS\Altium_Footprint_Lib.PcbLib; Height: 0.26MM; Library Path: Y:\MIS_DATABASE\Library\ALTIUM_TOOL\SCHEMATICS_PARTS\MS_DISCRETE_Library.schlib; Mfr_name: YAGEO AMERICA; Mfr_part_number: RC0201JR-072K2L; Mistral Part No: 110009030427-R; Package: 0201; Part_type: RESISTORS\FIXED; Project: GOLDEN-I LITE; RoHS: RoHS; Temperature: -55°C+125°C; Tolerance: 5%; Voltage: NA; Wattage: 1/20W; Weight: 0.17mg; Datasheet: Y:\MIS_DATABASE\DATASHEETS\RESISTORS\RCXXXXL-SER_MAR18.PDF
R339 = RESISTOR: RES 5.76K 1/10W 1% 0402; Chkd/date: MAZHAR/150709; Crtd /date: USMAN/220808; Custom_Duty: 15%; Customs_HS_Code: 85332119; Distributor_name: DIGIKEY; Distributor_part_number: P5.76KLCT-ND; Footprint Path: Y:\MIS_DATABASE\Library\ALTIUM_TOOL\PCB_FOOTPRINTS\Altium_Footprint_Lib.PcbLib; Height: 0.40MM; Library Path: Y:\MIS_DATABASE\Library\ALTIUM_TOOL\SCHEMATICS_PARTS\MS_DISCRETE_Library.schlib; Mfr_name: PANASONIC-ECG; Mfr_part_number: ERJ-2RKF5761X; Mistral Part No: 110009030945-R; Package: 0402; Part_type: RESISTORS\FIXED; Project: CPB; RoHS: RoHS; Temperature: -55°C+155°C; Tolerance: 1%; Voltage: NA; Wattage: 1/10W; Weight: 0.8mg; Datasheet: Y:\MIS_DATABASE\DATASHEETS\RESISTORS\PAN-ERJSER_NOV17.PDF
R351 = RESISTOR: RES 10K 1/10W 1% AUTO 0402; Chkd/date: MANIRAJA/191020; Crtd /date: ALVY/191020; Custom_Duty: 15%; Customs_HS_Code: 85332119; Distributor_name: DIGIKEY; Distributor_part_number: MCS0402-10.0K-MFCT-ND; Footprint Path: Y:\MIS_DATABASE\Library\ALTIUM_TOOL\PCB_FOOTPRINTS\Altium_Footprint_Lib.PcbLib; Height: 0.37MM; Library Path: Y:\MIS_DATABASE\Library\ALTIUM_TOOL\SCHEMATICS_PARTS\MS_DISCRETE_Library.schlib; Mfr_name: VISHAY; Mfr_part_number: MCS0402MC1002FE000; Mistral Part No: 110020100039-R; Package: 0402; Part_type: RESISTORS\FIXED; Project: MCX_80MHz_ADC_DRIVER; RoHS: RoHS; Temperature: -55°C+175°C; Tolerance: 1%; Voltage: NA; Wattage: 1/10W; Weight: 0.65mg; Datasheet: Y:\MIS_DATABASE\DATASHEETS\RESISTORS\MCTXXXXM-SER.PDF
TP24 TP26 TP27 = TESTPOINT: TESTPOINT CIR 20 SMD; Chkd/date: SHREESHAIL/171006; Crtd /date: MAZHAR/171006; Custom_Duty: NA; Customs_HS_Code: NA; Distributor_name: NA; Distributor_part_number: NA; Footprint Path: Y:\MIS_DATABASE\Library\ALTIUM_TOOL\PCB_FOOTPRINTS\Altium_Footprint_Lib.PcbLib; Height: NA; Library Path: Y:\MIS_DATABASE\Library\ALTIUM_TOOL\SCHEMATICS_PARTS\MS_DISCRETE_Library.schlib; MECHANICAL 3D STEP FILE: NA; Manufacturer: LOCAL; Mfr_name: LOCAL; Mistral Part No: NA; Package: SMD; Project: BT MODULE_CSRBC04; RoHS: NA; Temperature: NA; Tolerance: NA; Voltage: NA; Wattage: NA; Weight: NA; Datasheet: NA
U41 = SN74LVC1G11DCKR_SC70-6: IC SINGLE 3-INPUT POSITIVE-AND GATE SON6; Chkd/date: MANIRAJA/270121; Crtd /date: ALVY/270121; Custom_Duty: 15%; Customs_HS_Code: 85423100; Distributor_name: DIGIKEY; Distributor_part_number: 296-30120-1-ND; Footprint Path: Y:\MIS_DATABASE\Library\ALTIUM_TOOL\PCB_FOOTPRINTS\Altium_Footprint_Lib.PcbLib; Height: 0.60MM; Library Path: Y:\MIS_DATABASE\Library\ALTIUM_TOOL\SCHEMATICS_PARTS\MS_GATE_Library.schlib; Mfr_name: TEXAS INSTRUMENTS; Mistral Part No: 141021010013-R; Package: SON6; Part_type: ICS\DIGITAL\GATES; Project: AM64X_SKEVM; RoHS: RoHS; Temperature: -40°C+125°C; Tolerance: NA; Voltage: NA; Wattage: NA; Weight: 33mg; Datasheet: Y:\MIS_DATABASE\DATASHEETS\ICS\DIGITAL\GATES\SN74LVC1G_NOV16.PDF
U78 = DP83867IRRGZ_VQFN48: IC HIGH IMMUNITY 10/100/1000 Mb/s ETHERNET PHY LAYER TRANSCEIVER VQFN48; Chkd/date: MANIRAJA/110817; Crtd /date: MANIRAJA/110817; Custom_Duty: 15%; Customs_HS_Code: 85423100; Distributor_name: DIGIKEY; Distributor_part_number: DP83867IRRGZT-ND; Height: 1.00MM; Mfr_name: TEXAS INSTRUMENTS; Mistral Part No: 143017080002-R; Package: VQFN48; Part_type: ICS\TELECOM\TRANSCEIVER; Project: TI_SVB_CONTROLLER CARD; RoHS: RoHS; Temperature: -40°C+85°C; Tolerance: NA; Voltage: NA; Wattage: NA; Weight: NA; Datasheet: Y:\MIS_DATABASE\DATASHEETS\ICS\DIGITAL\BUSTRANSCEIVER\DP83867I.PDF
U18 = AM62A-EVM_SOC_FCBGA484: IC AM62A SK EVM SoC MICROPROCESSOR FCBGA484; Chkd/date: PRADEEP/020823; Crtd /date: PRADEEP/020823; Custom_Duty: 15%; Customs_HS_Code: 85423100; Distributor_name: NA; Distributor_part_number: NA; Footprint Path: Y:\MIS_DATABASE\Library\ALTIUM_TOOL\PCB_FOOTPRINTS\Altium_Footprint_Lib.PcbLib; Height: 2.65MM; Library Ref: AM62A-EVM_SoC_FCBGA484; Mfr_name: TEXAS INSTRUMENTS; Mistral Part No: 141230080001-R; Package: FCBGA484; Part_type: ICS\DIGITAL\MICROPROCESSOR; Project: TI_AM62A_SK_EVM; RoHS: NA; Temperature: NA; Tolerance: NA; Voltage: NA; Wattage: NA; Weight: NA; Datasheet: Y:\MIS_DATABASE\DATASHEETS\ICS\DIGITAL\MICROCONTROLLER\AM62A_SK_EVM.PDF

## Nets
DGND: C21.2 C26.1 C35.1 C43.2 C48.2 C49.2 C50.2 C54.2 C55.2 C58.2 C59.2 C60.2 C61.2 C62.2 C63.2 C67.2 C75.2 C87.1 C111.2 C127.2 C191.2 C195.2 C199.2 C267.2 C281.2 C293.2 C296.2 C297.2 C300.2 C307.1 C310.2 C311.2 C312.2 C313.2 C346.2 J6.1(CH-GND) Q5.4(S1) Q5.7(S2) Q6.4(S1) Q6.7(S2) Q7.4(S1) Q7.7(S2) R63.2 R64.2 R93.1 R96.1 R121.2 R129.2 R154.2 R155.2 R156.2 R174.2 R305.2 R311.2 R333.1 R334.1 R336.1 R337.1 R340.1 R351.2 R440.2 U11.3(GND) U12.B3(GND) U12.C1(VSSQ) U12.E5(VSSQ) U16.2(GND) U29.2(GND) U38.4(GND) U38.9(EPAD) U41.2(GND) U78.49(GND) ; also on sheet 9 10 11 12 13 14 15 16 17 18 19 23 24 25 26 27 28 29 30 31 32 33 34 35 36 37 38 39 40 41 42 43
VCC1V8_SYS: C21.1 C26.2 C191.1 C195.1 C199.1 R41.2 R46.2 R49.2 R295.2 R296.2 R297.2 R299.2 R300.2 R301.2 R302.2 R303.2 R304.2 R306.2 U11.5(VCC) U12.B4(VCC) U12.D1(VCCQ) U12.E4(VCCQ) ; also on sheet 12 13 17 18 33 36 38 39 41
VCC_3V3_SYS: C35.2 C43.1 C61.1 C62.1 C75.1 C87.2 C111.1 C127.1 C281.1 C297.1 C310.1 C311.1 FL11.1 R83.2 R84.2 R85.2 R86.2 R151.1 R175.2 R176.2 R330.1 R335.2 R339.1 R346.2 R347.2 R354.2 R355.1 R366.2 R367.2 U16.4(V+) U29.4(V+) U38.8(VCC) U41.5(VCC) U78.19(VDDIO) U78.30(VDDIO) U78.41(VDDIO) ; also on sheet 9 10 12 13 17 18 19 23 25 26 28 29 30 32 33 34 35 36 37 38 39 40 41 42
VDD_1V0: C48.1 C49.1 C50.1 C58.1 C59.1 C60.1 C267.1 C296.1 C312.1 C313.1 U78.6(VDD1P0) U78.24(VDD1P0) U78.31(VDD1P0) U78.42(VDD1P0) ; also on sheet 10 23
VDD_2V5: C54.1 C55.1 C63.1 C67.1 C293.1 C300.1 U78.3(VDDA2P5) U78.9(VDDA2P5) ; also on sheet 10 23
CPSW1_GPIO_0: J6.14 Q7.1(D1) Q7.2(D2) Q7.5(D3) Q7.6(D4) Q7.8(D5) R367.1
CPSW1_LED_1000: J6.12 Q5.1(D1) Q5.2(D2) Q5.5(D3) Q5.6(D4) Q5.8(D5)
CPSW1_LED_ACT: J6.13 Q6.1(D1) Q6.2(D2) Q6.5(D3) Q6.6(D4) Q6.8(D5) R366.1
CPSW_ETH1_D0N: J6.10(MX0-) U78.2(TD_M_A)
CPSW_ETH1_D0P: J6.9(MX0+) U78.1(TD_P_A)
CPSW_ETH1_D1M: J6.8(MX1-) U78.5(TD_M_B)
CPSW_ETH1_D1P: J6.7(MX1+) U78.4(TD_P_B)
CPSW_ETH1_D2M: J6.6(MX2-) U78.8(TD_M_C)
CPSW_ETH1_D2P: J6.5(MX2+) U78.7(TD_P_C)
CPSW_ETH1_D3M: J6.4(MX3-) U78.11(TD_M_D)
CPSW_ETH1_D3P: J6.3(MX3+) U78.10(TD_P_D)
CPSW_ETH1_GPIO_0: R83.1 R334.2 R342.1 R365.1 TP20.1(TP)
CPSW_ETH1_GPIO_1: R84.1 R333.2 R341.1 TP21.1(TP)
CPSW_ETH1_LED0: TP18.1(TP) U78.47(LED_0)
CPSW_ETH1_LED_1000: R86.1 R327.1 R336.2 TP23.1(TP) U78.46(LED_1)
CPSW_ETH1_LED_ACT: R85.1 R337.2 R364.1 TP22.1(TP) U78.45(LED_2)
CPSW_ETH_INTn: R78.1 ; also on sheet 41
CPSW_RGMII1_ETH1_CLK: U78.15(XI) ; also on sheet 24
CPSW_RGMII1_ETH1_CLK_OUT: TP28.1(TP) U78.18(CLK_OUT)
CPSW_RGMII1_ETH1_RBIAS: C307.2 R351.1 U78.12(RBIAS)
CPSW_RGMII1_MDC: R108.2 R354.1 U78.16(MDC)
CPSW_RGMII1_MDIO: R107.2 R355.2 U78.17(MDIO)
CPSW_RGMII1_RD0: R96.2 R347.1 U78.33(RX_D0) ; also on sheet 24
CPSW_RGMII1_RD1: U78.34(RX_D1) ; also on sheet 24
CPSW_RGMII1_RD2: R93.2 R346.1 U78.35(RX_D2) ; also on sheet 24
CPSW_RGMII1_RD3: U78.36(RX_D3) ; also on sheet 24
CPSW_RGMII1_RESETn: R440.1 U41.4(Y) U78.43(RESET_N)
CPSW_RGMII1_RX_CTL: R339.2 R340.2 U78.38(RX_DV/RX_CTRL) ; also on sheet 24
CPSW_RGMII1_RXC: R348.1 ; also on sheet 24
CPSW_RGMII1_TD0: U78.28(TX_D0) ; also on sheet 24
CPSW_RGMII1_TD1: U78.27(TX_D1) ; also on sheet 24
CPSW_RGMII1_TD2: U78.26(TX_D2) ; also on sheet 24
CPSW_RGMII1_TD3: U78.25(TX_D3) ; also on sheet 24
CPSW_RGMII1_TX_CTL: U78.37(TX_EN/TX_CTRL) ; also on sheet 24
CPSW_RGMII1_TXC: U78.29(GTX_CLK) ; also on sheet 24
CPSW_RGMII_INTn: R78.2 R335.1 U78.44(INT/PWDN) ; also on sheet 23
EEPROM_A0: R151.2 U38.1(A0)
EEPROM_A1: R154.1 U38.2(A1)
EEPROM_A2: R156.1 U38.3(A2)
EEPROM_WP: R155.1 U38.7(WP)
ETH1_EARTH: C346.1 J6.15(SH1) J6.16(SH2) R121.1
EXP_GPIO0_14_LT: U18.G20(OSPI0_CSN3) ; also on sheet 33
GPIO_CPSW1_RST: R174.1 R175.1 U41.1(A) ; also on sheet 39
GPIO_OSPI_RSTn: R41.1 U11.1(A) U18.G19(OSPI0_CSN1)
OSPI0_CSN0: R320.2 U18.H21(OSPI0_CSN0)
OSPI0_LBCLK: R312.2 R319.1
OSPI0_LBCLKO_R: R319.2 U18.K22(OSPI0_LBCLKO)
OSPI_CLK: R311.1 R313.1 U18.L22(OSPI0_CLK)
OSPI_CS: R304.1 R320.1 U12.C2(~{CS})
OSPI_DQ0: R299.1 RA1.2 U12.D3(IO0)
OSPI_DQ1: R302.1 RA2.1 U12.D2(IO1)
OSPI_DQ2: R303.1 RA2.2 U12.C4(IO2/~{WP})
OSPI_DQ3: R300.1 RA1.3 U12.D4(IO3)
OSPI_DQ4: R301.1 RA2.4 U12.D5(IO4)
OSPI_DQ5: R297.1 RA1.4 U12.E3(IO5)
OSPI_DQ6: R296.1 RA2.3 U12.E2(IO6)
OSPI_DQ7: R295.1 RA1.1 U12.E1(IO7)
OSPI_DQS: R305.1 R306.1 R309.1 U12.C3(DS)
OSPI_DQS_SOC: R309.2 R312.1 U18.L21(OSPI0_DQS)
OSPI_INTn: R49.1 R50.1 U18.K20(OSPI0_CSN2)
OSPI_RSTn: R46.1 U11.4(Y) U12.A4(~{RESET})
PORz_OUT: U41.3(B) ; also on sheet 19 23 26 41
RESETSTATz: R173.1 U11.2(B) ; also on sheet 18 19 23 26 37 38 39 40 41
SoC_I2C0_SCL: U38.6(SCL) ; also on sheet 9 12 32 41
SoC_I2C0_SDA: U38.5(SDA) ; also on sheet 9 12 32 41
SOC_I2C1_SCL: TP49.1(TP) U16.1(SCL) U29.1(SCL) ; also on sheet 13 25 38 39 40 41
SOC_I2C1_SDA: TP50.1(TP) U16.6(SDA) U29.6(SDA) ; also on sheet 13 25 38 39 40 41
SoC_OSPI_DQ0: RA1.7 U18.J21(OSPI0_D0)
SoC_OSPI_DQ1: RA2.8 U18.J18(OSPI0_D1)
SoC_OSPI_DQ2: RA2.7 U18.J19(OSPI0_D2)
SoC_OSPI_DQ3: RA1.6 U18.H18(OSPI0_D3)
SoC_OSPI_DQ4: RA2.5 U18.K21(OSPI0_D4)
SoC_OSPI_DQ5: RA1.5 U18.H19(OSPI0_D5)
SoC_OSPI_DQ6: RA2.6 U18.J20(OSPI0_D6)
SoC_OSPI_DQ7: RA1.8 U18.J22(OSPI0_D7)
SoC_RGMII_MDC: R108.1 ; also on sheet 23 31
SoC_RGMII_MDIO: R107.1 ; also on sheet 23 31
TMP1_ADD0: R64.1 U16.5(ADD0)
TMP1_ADD1: R63.1 U16.3(ADD1)
TMP2_ADD1: R129.1 U29.3(ADD1)
N16960546: R313.2 U12.B2(CLK)
N17110597: TP26.1(TP) U78.13(VDDA1P8)
N17133547: FL11.2 J6.2(VCC)
N17137240: J6.11 R330.2
N17167245: R348.2 U78.32(RX_CLK)
N17269599: R173.2 R176.1 U41.6(C)
N17653582: Q5.3(G) R327.2
N17796705: Q6.3(G) R364.2
N17796716: Q7.3(G) R365.2
N18576337: R342.2 U78.39(GPIO_0)
N18576340: R341.2 U78.40(GPIO_1)
N21016640: TP24.1(TP) U78.48(VDDA1P8)
N21079949: TP27.1(TP) U78.14(XO)
N22124383: R50.2 U12.A5(NC3)

Not connected (* = marked no-connect by the designer): U12 A2(NC1)* A3(NC2)* B1(NC4)* B5(NC5)* C5(NC6)*; U29 5(ADD0)*; U78 20(JTAG_CLK)* 21(JTAG_TDO)* 22(JTAG_TMS)* 23(JTAG_TDI)*

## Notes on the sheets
sheet 20
- OSPI  FLASH
- D-Note :-
  Connecting OSPI interface to
  multiple devices is not
  recommended or supported
- R-Note :-
  SOC IO buffers are off during power-up. A pullup is
  recommended near to the attached device, to hold the
  attached device IOs in a known state. Use of Pullups are
  attached device dependent
- R-Note :-
  These 0 O resistors are used for
  configuring QSPI and OSPI
  This is optional during custom
  board design
- SOC OSPI INTERFACE
- CAD Note :-
  Place OSPI clock
  series resistor
  near to the SOC
  clock output
- Cad Note :-
  Place series
  resistor close to
  the Memory
- CAD Note :-
  Place SOC clock
  output pulldown
  resistor near to the
  clock input pin of
  the attached
  (memory) device
- D-Note :-
  OSPI_INTn connection is
  provided to match the
  requirement of Alternate part
- Cad Note :-
  Place
  pulldown
  closer to
  the SOC
- CAD Note :-
  Place R312 close
  to the Memory to
  avoid stub
- D-Note :-
  External  loopback
  clock series
  resistors are DNI
  when DQS is connected
- CAD Note :-
  Place R319 close to the SOC Ball
  with as little trace as possible
- R-Note :-
  DQS pulldown is
  enabled
- D-Note :-
  For QSPI Configuration DNI the following 0E resistors
  1.OSPI_DQ4 to OSPI_DQ7 nets
- OSPI  FLASH RESET
- D-Note :-
  Add a series resistor to the
  SOC GPIO input for isolation
  or testing. Refer SK-AM62P-LP
  schematics
- D-Note :-
  ANDing logic additionally performs
  level translation Verify the Reset
  IO level compatibility before
  optimizing the reset ANDing logic.
  IO level mismatch could cause
  supply leakage and affect SOC
  operation
sheet 21
- BOARD ID EEPROM
- I2C ADDRESS: 0X51
- DIGITAL TEMPERATURE SENSORS
- I2C ADDRESS: 0x48
- I2C ADDRESS: 0x49
- CAD NOTE: PLACE TEMP SENSOR CLOSE TO SoC
- CAD NOTE: PLACE TEMP SENSOR CLOSE TO LPDDR4
- Silk: SOC_I2C1
sheet 22
- D-Note :-
  The caps and values used are  as per
  the EPHY data sheet recommendations.
- CPSW3G RGMII 1 - ETHERNET PHY
- D-Note :-
  Refer to DP83867ERGZ-R-EVM when using LAN
  Discrete Transformer Module and RJ45 connector
- R-Note :-
  Ferrite is DNI
- D-Note :-
  Verify the power sequence
  requirements for Two-Supply
  Configuration and Three-Supply
  Configuration
- RJ45 CONNECTOR WITH
  INTEGRATED MAGNETICS
- 100E
- 100E
- 100E
- D-Note :-
  Provide provision for series
  resistor based on EPHY for
  RX signals near to EPHY
- 100E
- D-Note :-
  XI clock Input amplitude allowed
  is 1.8V irrespective of the IO
  supply. Use a CAP DIVIDER  when
  the clock amplified is 3.3V
- D-Note :-
  Refer EPHY EVM for
  JTAG connection
- D-Note :-
  Add a series resistor to the
  SOC GPIO input for isolation
  or testing. Refer SK-AM62P-LP
  schematics
- D-Note :-
  ANDing logic could be
  optimized to 2 input AND
  gate Use RESETSTATz (or
  PORz_OUT)  and the SOC IO
  as inputs
- D-Note :-
  ANDing logic additionally performs level
  translation Verify the Reset IO level
  compatibility before optimizing the reset
  ANDing logic. IO level mismatch could
  cause supply leakage and affect SOC
  operation
- R-Note :-
  Pullup is enabled for SOC GPIO input
  RESETSTATz series resistor is DNI
- Silk: RGMII-1
- PHY ADDRESS = 00000
- 10/100/1000 advertised, Auto-MDI-X
- Auto-negotiation Enabled
- Tx Clock Skew = 0ns
- Rx Clock Skew = 2ns
